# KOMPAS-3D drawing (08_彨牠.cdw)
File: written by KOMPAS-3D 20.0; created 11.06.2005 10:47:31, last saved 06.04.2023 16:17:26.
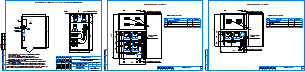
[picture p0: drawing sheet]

Sheets 1-3: A3, landscape

Document properties: Автор: ДВС; Организация: S&T; Разработал: Антошин; Проверил: Тарасов; Утвердил: Шмончев; Н. контр.: Силаков; Форматы листов документа: 3xA3; Полное имя файла: \\s-tech\depts\Отдел_ПКО\Проекты\Типовые проекты МКД 2023\!Типовой проект\1_Типовой проект МКД_RS-485\08_План.cdw

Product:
- Part/product: (unnamed)
  - Component: \\Helios\отдел_пко\Общая папка Компас\_Addons\Signatures\Signatures.lfr|Тарасов  | Полное имя файла: C:\Users\MAntoshin\AppData\Local\Temp\qlkzkl.frw; source file: C:\Program Files\ASCON\KOMPAS-3D V13\Libs\_Addons\Signatures\Signatures.lfr
  - Component: \\Helios\отдел_пко\Общая папка Компас\_Addons\Signatures\Signatures.lfr|Силаков  | Полное имя файла: C:\Users\MAntoshin\AppData\Local\Temp\eiczbt.frw; source file: C:\Program Files\ASCON\KOMPAS-3D V13\Libs\_Addons\Signatures\Signatures.lfr
  - Component: \\Helios\отдел_пко\Общая папка Компас\_Addons\Signatures\Signatures.lfr|Шмончев  | Полное имя файла: C:\Users\MAntoshin\AppData\Local\Temp\hsklda.frw; source file: C:\Program Files\ASCON\KOMPAS-3D V13\Libs\_Addons\Signatures\Signatures.lfr

Title block, sheet 1: designation: ВЛСТ 1277. 01. 000 С8; scale: 1:1; sheet number: 1; Количество листов документа: 3; organisation: АО ГК / "Системы и Технологии"; Форматы листов документа: A3; stored path: D:\User\Семёнов\Планы\СЭС\ПС№9 Подсобное хозяйство\ПС№9 Подсобное хозяйство.cdw; cell 302: Система учета электроэнергии (с организацией удаленного / сбора данных) потребителей; cell 303: Типовой проект ИСУЭ многоквартирного / дома с использованием проводного / канала связи RS-485; cell 304: План расположения оборудования / и проводок; cell 320: Р
Title block, sheet 2: sheet number: 2; sheet number: 3; stored path: Z:\МРСК Северо-Запада Псковэнерго\Типовой проект\Рабочая документация\С8_005_План_многоквартирный_дом_PLC.cdw
Title block, sheet 3: stored path: \\fs1.s-tech.ru\depts\Отдел_ПКО\Проекты\ГУП СК Ставрополькоммунэлектро\2021\Типовой проект\02_Рабочая документация\С8_001_План_многоквартирный_дом_УСПД.cdw; designation, second copy: ВЛСТ 1277. 01. 000 С8-

Referenced files in \\Helios\отдел_пко\Общая папка Компас\_Addons\Signatures\: Signatures.lfr|Тарасов, Signatures.lfr, Signatures.lfr|Силаков, Signatures.lfr|Шмончев
Referenced files in C:\Program Files\ASCON\KOMPAS-3D V13\Libs\_Addons\Signatures\: Signatures.lfr
Referenced files: qlkzkl.frw, eiczbt.frw, hsklda.frw
Referenced files in C:\Program Files\ASCON\KOMPAS-3D v20\Sys\: Graphic.lcs
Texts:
  Тарасов
  Силаков
  Шмончев
  Лит-Масса-Масштаб
  Материал-Предприятие
  Z-начало формы
  Z-конец формы
  Форматированный
  Courier New
  Цитаты
  Адрес
  Список определений
  Термин
  Обычный
  heading 2
  Body Text
  heading 1
  Normal
  Без имени
  Centerline
  Outline
  Этажный щит (4 счетчика)
  эксплуатационной документации оборудования.
  проекта к конкретному объекту.
  приборов учета т.е. при установке счетчиков ЭЭ дверца щитов должна легко закрываться, не
  должно возникать помех и сложностей с дальнейшим обслуживанием оборудования, смотровые окна
  щитов должны позволять абонентам выполнять просмотр данных со счетчиков и т.д.
  Существующие кабельные каналы
  Таблица 1 - Перечень оборудования
  поз.
  Кол-во
  Счетчик электроэнергии
  DIN рейка
  Автоматический выключатель
  Разветвительная коробка RS-485
  Разборные контактные
  соединения
  Шкаф УСПД
  GSM-антенна
  ВРУ
  План размещения проектируемого оборудования в помещении электрощитовой
  Этажный щит (2 счетчика)
  Коробка разветвительная RS-485
  Счетчик
  Сплошная тонкая с изломами
  Стили документа
  ANSI37
  План расположения
  оборудования и проводок
  Разраб.
  Н.контр.
  ПС "Сокольники" №76
  Антошин
  03 Рабочие чертежи основного комплекта. ГОСТ Р 21.1101-2009 Ф3
  Чертеж строит. Посл. листы.  ГОСТ Р 21.1101-2009 Ф6.
Dimensions and other numbers on the sheet: 35; 2; 3с5; 0,54; 0,065; 0,14; 0,105; 0,91; 1; 3; 4; 0,8; 0,3; 1,2; 0,6; 7; 1:1; 04.23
